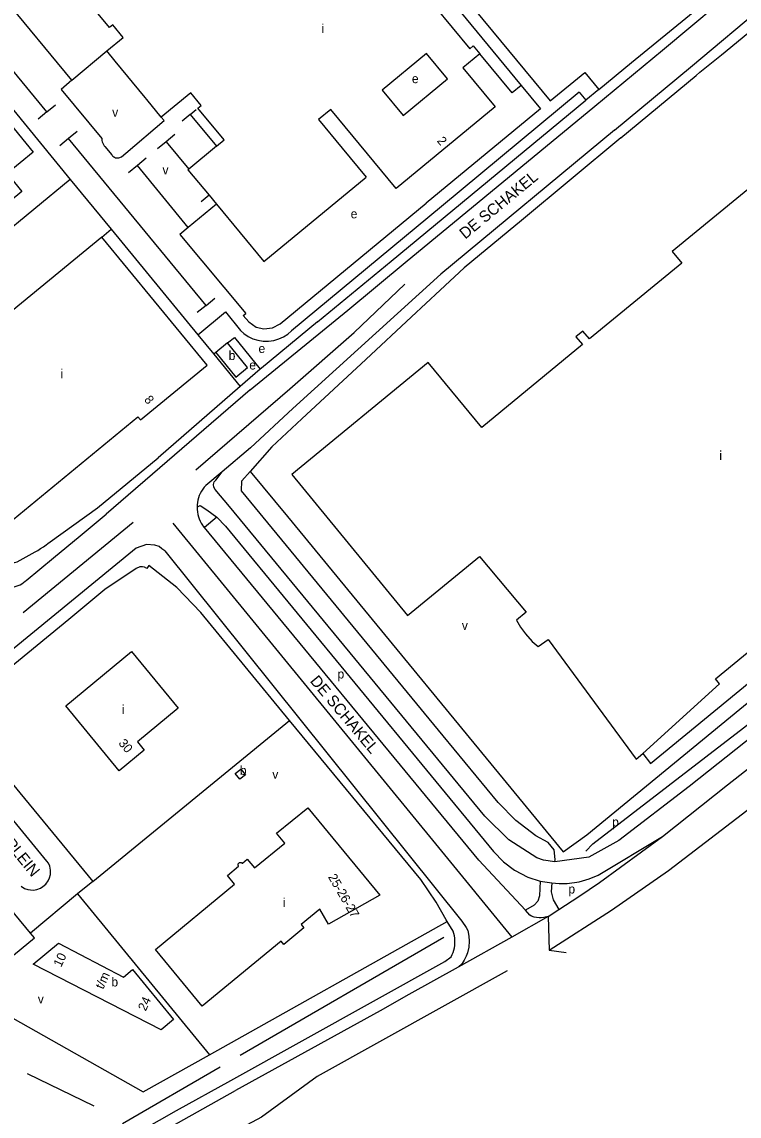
# Model space of a CAD drawing. Extents: x 156097 to 158136, y 385644 to 388348.
# Drawn here: x 157130.5 to 157447.6, y 386152 to 386635.8 of the extents above; entities that cross this region are included whole.
import ezdxf

# ---------------------------------------------------------------- set-up
doc = ezdxf.new("R2010")
doc.units = 0
for name, color, linetype in [('BLT_Basislijn', 7, 'Continuous'), ('BLT_Bebouwing', 7, 'Continuous'), ('BLT_Centroide', 7, 'Continuous'), ('BLT_Huisnummer', 7, 'Continuous'), ('BLT_Huisnummer_reeks', 7, 'Continuous'), ('BLT_Straatnaam', 7, 'Continuous'), ('BLT_Vlakafsluiter', 7, 'Continuous')]:
    doc.layers.add(name, color=color, linetype=linetype)

msp = doc.modelspace()

# ---------------------------------------------------------------- linework, layer by layer
at = {"layer": 'BLT_Basislijn'}
for p, q in [((157307.93, 386660.66), (157351.23, 386607.69)), ((157152.67, 386610.07), (157114.65, 386656.11)), ((157400.13, 386617.86), (157442.13, 386652.35)), ((157141.58, 386595.98), (157101.69, 386644.37)), ((157439.79, 386621.27), (157453.98, 386632.88)), ((157152.67, 386610.07), (157168.08, 386622.97)), ((157430.34, 386613.53), (157439.79, 386621.27)), ((157113.77, 386612.66), (157151.92, 386566.18)), ((157364.09, 386600.85), (157379.44, 386613.5)), ((157379.44, 386613.5), (157385.65, 386605.96)), ((157351.23, 386607.69), (157359.8, 386597.31)), ((157376.95, 386604.76), (157316.01, 386554.14)), ((157376.95, 386604.76), (157379.88, 386601.21)), ((157385.65, 386605.96), (157379.88, 386601.21)), ((157141.58, 386595.98), (157145.44, 386599.16)), ((157204.95, 386594.89), (157207.56, 386597.06)), ((157359.8, 386597.31), (157309.26, 386555.73)), ((157141.58, 386595.98), (157137.72, 386592.8)), ((157204.95, 386594.89), (157201.38, 386591.93)), ((157204.95, 386594.89), (157216.54, 386580.83)), ((157155.02, 386587.41), (157151.16, 386584.23)), ((157151.16, 386584.23), (157147.3, 386581.05)), ((157211.97, 386510.45), (157151.16, 386584.23)), ((157194.36, 386582.82), (157190.5, 386579.64)), ((157198.22, 386586), (157194.36, 386582.82)), ((157194.36, 386582.82), (157204.31, 386570.74)), ((157395.35, 386584.51), (157351.41, 386548.04)), ((157167.2, 386580.74), (157170.25, 386577.07)), ((157174.54, 386576.14), (157176.52, 386577.77)), ((157185.46, 386575.49), (157181.61, 386572.31)), ((157181.61, 386572.31), (157177.75, 386569.13)), ((157204.13, 386544.97), (157181.61, 386572.31)), ((157151.92, 386566.18), (157061.8, 386491.91)), ((157151.92, 386566.18), (157170.03, 386544.13)), ((157213.31, 386559.16), (157209.78, 386556.25)), ((157216.6, 386555.17), (157204.13, 386544.97)), ((157244.72, 386502.35), (157309.26, 386555.73)), ((157316.01, 386554.14), (157249.72, 386499.15)), ((157165.83, 386540.68), (157170.03, 386544.13)), ((157170.03, 386544.13), (157208.33, 386497.49)), ((157204.13, 386544.97), (157200.33, 386541.83)), ((157351.41, 386548.04), (157345.51, 386543.15)), ((157200.33, 386541.83), (157229.49, 386506.92)), ((157211.97, 386510.45), (157208.11, 386507.27)), ((157211.97, 386510.45), (157215.83, 386513.63)), ((157228.35, 386505.99), (157229.49, 386506.92)), ((157231.49, 386473.13), (157274.65, 386508.3)), ((157302.82, 386505.38), (157282.54, 386486.51)), ((157261.28, 386503.21), (157236.42, 386482.76)), ((157208.33, 386497.49), (157215.41, 386488.86)), ((157216.28, 386489.57), (157215.41, 386488.86)), ((157215.41, 386488.86), (157227.08, 386474.64)), ((157235.91, 386482.32), (157227.08, 386474.64)), ((157236.42, 386482.76), (157235.91, 386482.32)), ((157231.49, 386473.13), (157167.84, 386418.13)), ((157227.08, 386474.64), (157190.77, 386443.07)), ((157163.96, 386421), (157190.77, 386443.07)), ((157219.05, 386436.9), (157211.84, 386430.82)), ((157231.53, 386437.02), (157247.93, 386417.09)), ((157143.1, 386405.97), (157163.96, 386421)), ((157156.31, 386408.58), (157167.84, 386418.13)), ((157131.12, 386374.59), (157179.77, 386414.64)), ((157216.74, 386416.86), (157211.22, 386412.23)), ((157211.22, 386412.23), (157210.64, 386412.93)), ((157161.9, 386255.78), (157248.93, 386326.95)), ((157359.73, 386255.79), (157364.82, 386255.12)), ((157367.88, 386243.33), (157376.74, 386249.12)), ((157363.17, 386240.25), (157367.88, 386243.33)), ((157213.51, 386179.13), (157318.57, 386237.99)), ((157227.1, 386178.93), (157317.07, 386231.1)), ((157106.49, 386206.51), (157184.23, 386162.73)), ((157184.23, 386162.73), (157213.51, 386179.13)), ((157175.03, 386148.74), (157218.23, 386173.79)), ((157132.85, 386170.83), (157162.37, 386156.55)), ((157198.96, 386154.43), (157222.89, 386167.72)), ((157142.88, 386117.42), (157224.95, 386163.23))]:
    msp.add_line(p, q, dxfattribs=at)
for points in [[(157383.79, 386598.53), (157413.76, 386623.26), (157450.46, 386654.06)], [(157327.25, 386645.55), (157364.09, 386600.85)], [(157392.5, 386587.97), (157426.08, 386615.86), (157459.83, 386644.09)], [(157351.23, 386607.69), (157347.24, 386604.39), (157333, 386621.65)], [(157385.65, 386605.96), (157400.13, 386617.86)], [(157395.35, 386584.51), (157428.66, 386612.16), (157430.34, 386613.53)], [(157152.67, 386610.07), (157147.86, 386605.98), (157165.84, 386584.23), (157165.83, 386583.98), (157165.9, 386583.35), (157166.05, 386582.73), (157166.27, 386582.13), (157166.57, 386581.57), (157166.93, 386581.04), (157167.2, 386580.74)], [(157261.28, 386503.21), (157293.78, 386529.95), (157379.88, 386601.21)], [(157274.65, 386508.3), (157300.06, 386529.46), (157383.79, 386598.53)], [(157176.52, 386577.77), (157193.49, 386592.15), (157192.17, 386593.74)], [(157392.5, 386587.97), (157315.83, 386524.28), (157250.34, 386464.82), (157231.62, 386447.51), (157219.05, 386436.9)], [(157170.25, 386577.07), (157170.49, 386576.74), (157170.79, 386576.44), (157171.15, 386576.16), (157171.54, 386575.94), (157171.98, 386575.77), (157172.43, 386575.67), (157172.9, 386575.65), (157173.35, 386575.68), (157173.79, 386575.79), (157174.19, 386575.94), (157174.54, 386576.14)], [(157345.51, 386543.15), (157326.05, 386526.99), (157315.5, 386517.18)], [(157207.49, 386437.81), (157249.07, 386473.62), (157277.52, 386498.52), (157299.82, 386519.85)], [(157315.5, 386517.18), (157302.82, 386505.38)], [(157208.33, 386497.49), (157220.5, 386507.65), (157227.17, 386499.37)], [(157228.35, 386505.99), (157230.88, 386503.14), (157234.1, 386500.9), (157237.52, 386500.11), (157241.35, 386500.6), (157244.72, 386502.35)], [(157221.44, 386493.87), (157224.5, 386496.28), (157235.91, 386482.32)], [(157227.17, 386499.37), (157228.73, 386497.97), (157230.56, 386496.74), (157232.61, 386495.74), (157234.84, 386495.02), (157237.2, 386494.65), (157239.6, 386494.62), (157241.96, 386494.96), (157244.2, 386495.62), (157246.28, 386496.58), (157248.12, 386497.78), (157249.72, 386499.15)], [(157937.31, 386498.26), (157929.35, 386493.62), (157913.68, 386485.54), (157887.98, 386473.7), (157862.69, 386463.97), (157837.34, 386456.48), (157811.18, 386450.49), (157745.59, 386438.15), (157692.14, 386428.15), (157682, 386426.22), (157658.89, 386420.9), (157603.36, 386403.5), (157581.12, 386394.09), (157561.95, 386385.19), (157542.55, 386375.42), (157524.92, 386365.84), (157505.55, 386355.55), (157488.03, 386344.94), (157471.92, 386333.99), (157454.7, 386320.86), (157425.56, 386297.7), (157394.41, 386273.85)], [(157282.54, 386486.51), (157254.31, 386460.25), (157241.06, 386447.86), (157231.53, 386437.02)], [(157366.22, 386264.38), (157361.14, 386265.14), (157358.2, 386266.14), (157345.76, 386274.19), (157335.18, 386284.58), (157222.4, 386421.6), (157216.01, 386429.03), (157215.4, 386430.09), (157215.26, 386431.2), (157215.62, 386432.45), (157216.31, 386433.24), (157219.05, 386436.9)], [(157366.22, 386264.38), (157366.3, 386265.46), (157365.85, 386269.66), (157363.29, 386273.03), (157357.76, 386275.96), (157348.94, 386282.74), (157341.13, 386290.68), (157316.8, 386320.19), (157227.69, 386428.5), (157227.85, 386432.82), (157231.53, 386437.02)], [(157211.84, 386430.82), (157211.14, 386430.02), (157210.5, 386429.18), (157209.93, 386428.28), (157209.42, 386427.35), (157208.99, 386426.38), (157208.64, 386425.39), (157208.35, 386424.36), (157208.15, 386423.32), (157208.03, 386422.27), (157207.98, 386421.21), (157208.02, 386420.15), (157208.13, 386419.1), (157208.33, 386418.06), (157208.6, 386417.03), (157208.95, 386416.03), (157209.37, 386415.06), (157209.87, 386414.12), (157210.43, 386413.23), (157210.64, 386412.93)], [(157208.45, 386421.57), (157209.39, 386421.95), (157212.36, 386420.07), (157216.74, 386416.86)], [(157379.83, 386269.15), (157382.98, 386272.4), (157482.89, 386349.34), (157498.88, 386358.13), (157535.09, 386377.98), (157560.94, 386391.26), (157590.86, 386404.43), (157631.12, 386418.48)], [(157197.26, 386414.23), (157314.77, 386270.76), (157347.16, 386231.04)], [(157216.74, 386416.86), (157220.52, 386412.82), (157339.07, 386268.95), (157343.41, 386264.44), (157348.35, 386260.72), (157354.21, 386257.65), (157359.73, 386255.79)], [(157247.93, 386417.09), (157369.83, 386268.89), (157380.33, 386276.36), (157470.15, 386350.15)], [(157107.84, 386410.44), (157109.75, 386408.44), (157112.91, 386405.54), (157115.63, 386403.28), (157118.46, 386401.21), (157120.92, 386399.59), (157125.24, 386397.16), (157125.89, 386396.89), (157126.53, 386396.75), (157127.22, 386396.74), (157127.84, 386396.86), (157128.45, 386397.09), (157136.44, 386401.46), (157137.57, 386402.11), (157138.83, 386402.89), (157140.03, 386403.69), (157141.24, 386404.53), (157142.09, 386405.17), (157143.1, 386405.97)], [(157132.39, 386388.84), (157144.47, 386398.79), (157156.31, 386408.58)], [(157353.15, 386243.02), (157332.56, 386265.09), (157211.22, 386412.23)], [(157193.72, 386401.92), (157192.46, 386402.84), (157191.17, 386403.79), (157189.35, 386404.47), (157185.6, 386404.76), (157181.11, 386403.17), (157107.44, 386342.77)], [(157193.72, 386401.92), (157325.05, 386238.22), (157326.92, 386235.41)], [(157405.03, 386312.35), (157408.52, 386307.93), (157485.82, 386371.44), (157532.15, 386400.43)], [(157248.93, 386326.95), (157209.62, 386374.66), (157199.06, 386385.65), (157186.72, 386395.38), (157185.74, 386394.05), (157184.82, 386394.69), (157183.88, 386394.9), (157182.69, 386394.81), (157181.13, 386394.06), (157167.21, 386384.82), (157151.32, 386371.63), (157110.72, 386338.33)], [(157118.07, 386388.85), (157118.74, 386388.24), (157119.45, 386387.7), (157120.22, 386387.22), (157121.02, 386386.81), (157121.86, 386386.47), (157122.72, 386386.21), (157123.6, 386386.03), (157124.5, 386385.92), (157125.4, 386385.9), (157126.3, 386385.95), (157127.19, 386386.08), (157128.07, 386386.3), (157128.92, 386386.59), (157129.75, 386386.95), (157130.54, 386387.38), (157131.29, 386387.89), (157131.99, 386388.46), (157132.39, 386388.84)], [(157107.44, 386342.77), (157106.19, 386344.38), (157104.11, 386342.11), (157102.93, 386339.95), (157101.91, 386337.09), (157101.63, 386334.81), (157101.99, 386330.8), (157103.08, 386327.96), (157104.66, 386325.11), (157117.89, 386309.04), (157161.9, 386255.78)], [(157413.71, 386275.64), (157442.44, 386298.4), (157484.12, 386331.01)], [(157318.57, 386237.99), (157318.18, 386238.69), (157313.68, 386246.51), (157306.92, 386256.57), (157248.93, 386326.95)], [(157130.24, 386253.62), (157131.74, 386252.67), (157133.21, 386252.15), (157134.38, 386251.99), (157135.62, 386251.95), (157137.12, 386252.12), (157138.76, 386252.78), (157139.82, 386253.44), (157141.15, 386254.57), (157142.16, 386255.95), (157142.79, 386257.39), (157143.13, 386258.76), (157143.22, 386260.7), (157142.88, 386262.43), (157142.3, 386263.75), (157141.62, 386264.77), (157098.26, 386317.47)], [(157363.68, 386225.28), (157391.27, 386243.03), (157416.4, 386260.53), (157446.7, 386283.7), (157480.02, 386309.43)], [(157364.82, 386255.12), (157368.1, 386254.78), (157371.55, 386254.83), (157376.98, 386255.6), (157381.4, 386256.87), (157385.26, 386258.46), (157413.71, 386275.64)], [(157394.41, 386273.85), (157381.21, 386266.45), (157366.22, 386264.38)], [(157376.74, 386249.12), (157385.84, 386255.26), (157413.71, 386275.64)], [(157134.38, 386232.85), (157103.77, 386269.89)], [(157161.9, 386255.78), (157155.15, 386250.19)], [(157359.73, 386255.79), (157359.45, 386249.38), (157358.7, 386246.98), (157357.02, 386245.22), (157353.15, 386243.02)], [(157364.82, 386255.12), (157364.49, 386251.18), (157365.39, 386247.64), (157367.88, 386243.33)], [(157155.15, 386250.19), (157134.38, 386232.85)], [(157155.15, 386250.19), (157213.51, 386179.13)], [(157363.17, 386240.25), (157361.25, 386239.76), (157360.16, 386239.63), (157359.23, 386239.62), (157358.12, 386239.74), (157357, 386239.99), (157355.79, 386240.44), (157355.15, 386240.88), (157353.15, 386243.02)], [(157222.89, 386167.72), (157317.52, 386220.36), (157320.3, 386222.42), (157320.78, 386223.37), (157321.18, 386224.36), (157321.5, 386225.36), (157321.75, 386226.4), (157321.92, 386227.45), (157322.01, 386228.5), (157322.02, 386229.57), (157321.96, 386230.62), (157321.81, 386231.68), (157321.58, 386232.71), (157321.28, 386233.73), (157318.57, 386237.99)], [(157326.92, 386235.41), (157327.66, 386234.1), (157328.21, 386231.6), (157328.27, 386229.33), (157328.13, 386226.64), (157327.51, 386224.11), (157327.01, 386222.68), (157326.08, 386220.97), (157325.19, 386219.49), (157323.39, 386217.8)], [(157106.49, 386206.51), (157136.12, 386230.86), (157134.38, 386232.85)], [(157345.08, 386216.28), (157261.07, 386169.44), (157257.27, 386166.67), (157236.43, 386151.44), (157219.68, 386142.57), (157153.9, 386105.1)], [(157323.39, 386217.8), (157301.61, 386205.79), (157288.88, 386198.47), (157224.95, 386163.23)], [(157105, 386140.63), (157121.08, 386132.2), (157137.06, 386122.71), (157137.92, 386122.49), (157138.8, 386122.36), (157139.68, 386122.3), (157140.57, 386122.32), (157141.46, 386122.42), (157142.33, 386122.61), (157143.18, 386122.86), (157144, 386123.2), (157144.79, 386123.6), (157145.32, 386123.93), (157198.96, 386154.43)]]:
    msp.add_lwpolyline(points, dxfattribs=at)
at = {"layer": 'BLT_Bebouwing'}
for p, q in [((157171.77, 386618.49), (157168.08, 386622.97)), ((157185.05, 386602.38), (157171.77, 386618.49)), ((157185.78, 386601.5), (157185.05, 386602.38)), ((157192.17, 386593.74), (157185.78, 386601.5)), ((157208.36, 386597.72), (157209.77, 386598.89)), ((157219.96, 386583.66), (157208.36, 386597.72)), ((157216.54, 386580.83), (157219.96, 386583.66)), ((157216.54, 386580.83), (157204.31, 386570.74)), ((157213.31, 386559.16), (157216.6, 386555.17)), ((157402.18, 386309.76), (157405.03, 386312.35))]:
    msp.add_line(p, q, dxfattribs=at)
for points in [[(157168.08, 386622.97), (157175.3, 386628.92), (157170.68, 386634.51), (157169.27, 386633.34), (157154.66, 386651.06), (157160.35, 386655.75), (157150.91, 386667.21)], [(157306.66, 386653.54), (157305.19, 386652.34), (157328.57, 386623.97), (157330.05, 386625.19)], [(157318.67, 386610.65), (157309.49, 386621.79), (157289.89, 386605.63), (157299.07, 386594.49), (157318.67, 386610.65)], [(157333, 386621.65), (157325.56, 386615.52), (157339.73, 386598.21)], [(157330.05, 386625.19), (157333, 386621.65)], [(157135.47, 386578.26), (157123.98, 386568.81), (157130.53, 386560.85), (157115.81, 386548.73), (157109.24, 386556.7), (157077.52, 386530.62), (157069.93, 386539.82), (157044.43, 386518.9), (157028.49, 386538.25), (157112.11, 386606.77), (157135.47, 386578.26)], [(157209.77, 386598.89), (157205.19, 386604.48), (157192.17, 386593.74)], [(157267.16, 386597.04), (157261.75, 386592.58), (157272.2, 386579.91), (157282.73, 386567.14)], [(157295.95, 386562.12), (157267.16, 386597.04)], [(157339.73, 386598.21), (157295.95, 386562.12)], [(157473.82, 386558.12), (157463.54, 386570.55), (157463.83, 386570.81), (157459.65, 386575.91), (157453.55, 386570.87), (157457.23, 386566.4), (157418.11, 386534.29)], [(157204.31, 386570.74), (157203.98, 386570.47), (157213.31, 386559.16)], [(157216.6, 386555.17), (157237.49, 386529.84), (157282.73, 386567.14)], [(157165.83, 386540.68), (157079.79, 386470.01)], [(157079.79, 386470.01), (157108.67, 386434.94), (157110.04, 386436.12), (157126.75, 386415.79), (157181.86, 386461.2), (157183.01, 386459.8), (157212.51, 386484.05), (157165.83, 386540.68)], [(157418.11, 386534.29), (157422.31, 386529.18), (157381.43, 386495.61), (157378.57, 386499.08), (157375.51, 386496.55), (157378.38, 386493.09), (157333.84, 386456.47)], [(157221.44, 386493.87), (157216.28, 386489.57)], [(157225.14, 386478.78), (157230.32, 386483.04), (157221.44, 386493.87)], [(157216.28, 386489.57), (157225.14, 386478.78)], [(157333.84, 386456.47), (157310.22, 386485.25), (157249.88, 386435.72), (157301.07, 386373.34), (157332.87, 386399.43), (157353.51, 386374.81), (157349.15, 386371.23), (157351.04, 386368.12), (157353.2, 386365.2), (157356.19, 386361.9), (157358.74, 386359.58), (157363.24, 386362.68), (157402.18, 386309.76)], [(157437.19, 386345.33), (157500, 386396.91), (157522.28, 386415.19), (157526.01, 386410.62)], [(157178.95, 386357.42), (157199.6, 386332.32), (157181.61, 386317.48), (157184.59, 386313.82), (157173.5, 386304.66), (157149.92, 386333.4), (157178.95, 386357.42)], [(157405.03, 386312.35), (157438.92, 386343.05), (157437.19, 386345.33)], [(157227.31, 386305.36), (157229.37, 386302.86), (157226.96, 386300.89), (157224.91, 386303.4), (157227.31, 386305.36)], [(157257.02, 386288.24), (157288.75, 386249.7), (157266.1, 386236.82), (157262.28, 386243.44), (157254.08, 386236.66), (157255.23, 386235.26), (157246.3, 386227.92), (157245.15, 386229.36), (157210.23, 386200.57), (157189.57, 386225.68), (157224.58, 386254.49), (157221.38, 386258.33), (157226.34, 386262.46), (157226.29, 386262.55), (157226.24, 386262.64), (157226.2, 386262.73), (157226.17, 386262.82), (157226.15, 386262.92), (157226.14, 386263.01), (157226.14, 386263.09), (157226.14, 386263.17), (157226.15, 386263.24), (157226.17, 386263.37), (157226.21, 386263.48), (157226.29, 386263.64), (157226.39, 386263.78), (157226.48, 386263.87), (157226.57, 386263.95), (157226.74, 386264.05), (157226.9, 386264.12), (157227.09, 386264.16), (157227.28, 386264.16), (157227.46, 386264.13), (157227.6, 386264.09), (157227.71, 386264.04), (157227.8, 386263.98), (157227.92, 386263.89), (157228.01, 386263.8), (157230.21, 386265.6), (157233.38, 386261.74), (157246.73, 386272.73), (157243.15, 386277.09), (157257.02, 386288.24)], [(157146.8, 386228.46), (157175.45, 386213.41), (157179.39, 386216.77), (157197.57, 386194.67), (157192.1, 386190.17), (157135.48, 386219.16), (157146.8, 386228.46)]]:
    msp.add_lwpolyline(points, dxfattribs=at)
at = {"layer": 'BLT_Vlakafsluiter'}
for p, q in [((157363.17, 386240.25), (157347.16, 386231.04)), ((157363.17, 386240.25), (157363.68, 386225.28)), ((157347.16, 386231.04), (157323.39, 386217.8)), ((157363.68, 386225.28), (157371.13, 386224.39))]:
    msp.add_line(p, q, dxfattribs=at)

# ---------------------------------------------------------------- texts
at = {"layer": 'BLT_Centroide'}
for s, p in [('i', (157263, 386630.87)), ('e', (157302.96, 386608.73)), ('v', (157170.46, 386593.87)), ('v', (157192.72, 386568.41)), ('e', (157275.9, 386548.95)), ('e', (157235.15, 386489.41)), ('b', (157221.96, 386486.31)), ('i', (157147.62, 386478.25)), ('e', (157231.08, 386482.1)), ('i', (157438.9, 386442.09)), ('v', (157325.05, 386366.96)), ('p', (157270.07, 386345.48)), ('i', (157174.77, 386329.81)), ('b', (157226.91, 386302.85)), ('v', (157241.25, 386301.12)), ('p', (157391.5, 386280.06)), ('p', (157372.16, 386250.4)), ('i', (157245.88, 386244.41)), ('b', (157170.12, 386209.31)), ('v', (157137.58, 386201.78))]:
    msp.add_text(s, height=4, dxfattribs=at).set_placement(p)
at = {"layer": 'BLT_Huisnummer'}
for s, rotation, p in [('2', 309.5027, (157313.83, 386583.12)), ('30', 309.4854, (157173.03, 386316.76))]:
    msp.add_text(s, height=4, rotation=rotation, dxfattribs=at).set_placement(p)
at = {"layer": 'BLT_Huisnummer_reeks'}
for s, rotation, p in [('8', 309.4949, (157184.36, 386468.63)), ('25-26-27', 299.9856, (157265.78, 386257.73)), ('10', 65.2354, (157147.91, 386217.56)), ('t/m', 65.2354, (157166.43, 386207.79)), ('24', 65.2354, (157185.29, 386198.15))]:
    msp.add_text(s, height=4, rotation=rotation, dxfattribs=at).set_placement(p)
at = {"layer": 'BLT_Straatnaam'}
for s, rotation, p in [('DE SCHAKEL', 39.586, (157326.54, 386539.52)), ('DE SCHAKEL', 310.0736, (157257.68, 386344.23)), ('HET SCHAKELPLEIN', 309.3444, (157093.35, 386308.21))]:
    msp.add_text(s, height=5, rotation=rotation, dxfattribs=at).set_placement(p)

doc.saveas('drawing.dxf')
